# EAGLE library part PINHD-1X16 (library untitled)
PIN HEADER
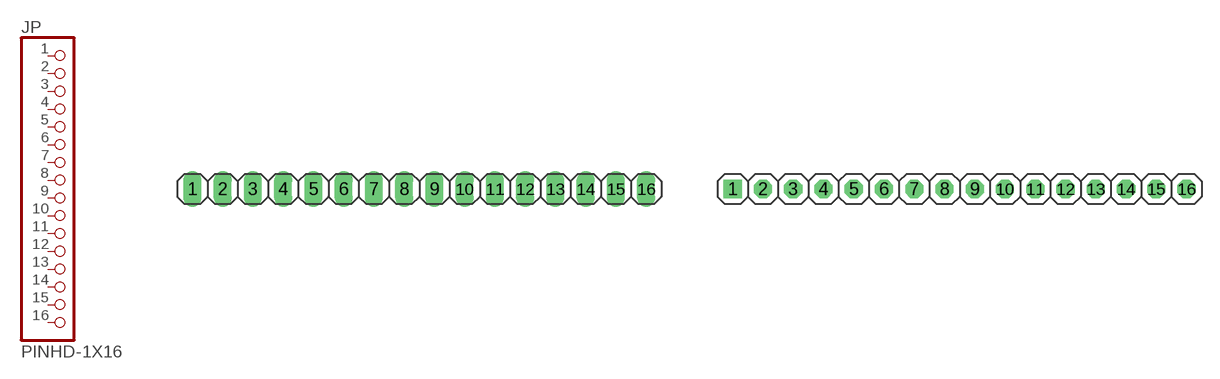
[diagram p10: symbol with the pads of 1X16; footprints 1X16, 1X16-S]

Designator prefix JP

## PINHD-1X16_2.54  [1X16]
1  1  pas
2  2  pas
3  3  pas
4  4  pas
5  5  pas
6  6  pas
7  7  pas
8  8  pas
9  9  pas
10  10  pas
11  11  pas
12  12  pas
13  13  pas
14  14  pas
15  15  pas
16  16  pas

## PINHD-1X16_2.54-S  [1X16-S]
Pads as for 1X16

## PINHD-1X16_2.54-90°  [1X16/90]
Pads as for 1X16

## PINHD-1X16_2.54-90°-S  [1X16/90-S]
Pads as for 1X16

## PINHD-1X16_2.00  [1X16M]
Pads as for 1X16

## PINHD-1X16_2.54-SMD  [1X16SMD]
Pads as for 1X16

## PINHD-1X16_2.54-SMD-90°  [1X16SMD/90]
Pads as for 1X16

## Footprint 1X16 (pad centres in mm)
PIN HEADER - 2.54
drill 1.016 long: 1 -19.05,0; 2 -16.51,0; 3 -13.97,0; 4 -11.43,0; 5 -8.89,0; 6 -6.35,0; 7 -3.81,0; 8 -1.27,0; 9 1.27,0; 10 3.81,0; 11 6.35,0; 12 8.89,0; 13 11.43,0; 14 13.97,0; 15 16.51,0; 16 19.05,0

## Footprint 1X16-S (pad centres in mm)
PIN HEADER - 2.54
drill 1.016 square: 1 -19.05,0
drill 1.016 octagon: 2 -16.51,0; 3 -13.97,0; 4 -11.43,0; 5 -8.89,0; 6 -6.35,0; 7 -3.81,0; 8 -1.27,0; 9 1.27,0; 10 3.81,0; 11 6.35,0; 12 8.89,0; 13 11.43,0; 14 13.97,0; 15 16.51,0; 16 19.05,0

## Footprint 1X16/90 (pad centres in mm)
PIN HEADER - 2.54 90°
drill 1.016 long: 1 -19.05,-3.81; 2 -16.51,-3.81; 3 -13.97,-3.81; 4 -11.43,-3.81; 5 -8.89,-3.81; 6 -6.35,-3.81; 7 -3.81,-3.81; 8 -1.27,-3.81; 9 1.27,-3.81; 10 3.81,-3.81; 11 6.35,-3.81; 12 8.89,-3.81; 13 11.43,-3.81; 14 13.97,-3.81; 15 16.51,-3.81; 16 19.05,-3.81

## Footprint 1X16/90-S (pad centres in mm)
PIN HEADER - 2.54 90°
drill 1.016 square: 1 -19.05,-3.81
drill 1.016 octagon: 2 -16.51,-3.81; 3 -13.97,-3.81; 4 -11.43,-3.81; 5 -8.89,-3.81; 6 -6.35,-3.81; 7 -3.81,-3.81; 8 -1.27,-3.81; 9 1.27,-3.81; 10 3.81,-3.81; 11 6.35,-3.81; 12 8.89,-3.81; 13 11.43,-3.81; 14 13.97,-3.81; 15 16.51,-3.81; 16 19.05,-3.81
